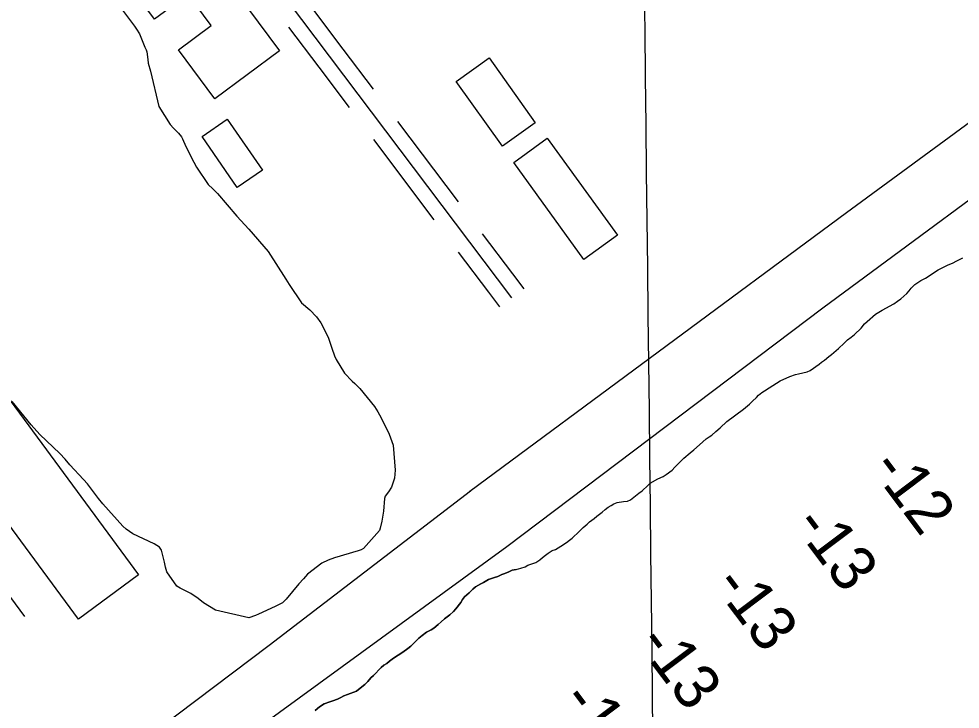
# Model space of a CAD drawing. Extents: x 3683613 to 3738215, y 469626 to 495384.
# Drawn here: x 3692332 to 3693268, y 490854 to 491540 of the extents above; entities that cross this region are included whole.
import ezdxf

# ---------------------------------------------------------------- set-up
doc = ezdxf.new("R2010")
doc.units = 0
for name, color, linetype in [('V-BLDG-OTLN', 7, 'Continuous'), ('V-GRID-MAJR', 7, 'Continuous'), ('V-LEVE-TOET', 7, 'Continuous'), ('V-ROAD-CNTR', 7, 'Continuous'), ('V-SITE-VEGE', 7, 'Continuous'), ('V-TOPO-SHOR', 7, 'Continuous'), ('V-TOPO-SPOT', 7, 'Continuous')]:
    doc.layers.add(name, color=color, linetype=linetype)

msp = doc.modelspace()

# ---------------------------------------------------------------- linework, layer by layer
at = {"layer": 'V-BLDG-OTLN'}
for points in [[(3692442.64, 491572.97000000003), (3692507.651, 491621.139), (3692591.333, 491508.2), (3692527.1890000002, 491460.677), (3692491.073, 491509.42100000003), (3692523.6180000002, 491533.534), (3692500.731, 491564.422), (3692467.318, 491539.664)], [(3692767.139, 491477.896), (3692799.823, 491501.163), (3692845.66, 491436.776), (3692812.9760000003, 491413.509)], [(3692539.414, 491440.41000000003), (3692574.386, 491389.74), (3692549.488, 491372.555), (3692514.52, 491423.227)], [(3692927.481, 491325.169), (3692894.085, 491300.976), (3692824.285, 491397.33400000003), (3692857.681, 491421.527)], [(3692184.004, 491350.224), (3692451.291, 490987.378), (3692391.522, 490943.35000000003), (3692124.237, 491306.196)]]:
    msp.add_lwpolyline(points, close=True, dxfattribs=at)
at = {"layer": 'V-GRID-MAJR'}
msp.add_spline([(3693141.066, 475101.816), (3693072.329, 481160.385), (3693003.5700000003, 487220.886), (3692934.811, 493281.396), (3692934.789, 493283.31700000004)], degree=3, dxfattribs=at)
at = {"layer": 'V-LEVE-TOET'}
for points in [[(3692780.816, 491070.70900000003), (3693154.944, 491347.748), (3693544.7460000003, 491633.896)], [(3693375.608, 491432.818), (3693131.521, 491252.477), (3692817.579, 491015.343)], [(3692069.132, 490545.9), (3692088.7970000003, 490552.982), (3692103.804, 490559.405), (3692117.5300000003, 490568.152), (3692133.363, 490579.45300000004), (3692229.812, 490654.031), (3692399.091, 490780.204), (3692581.236, 490917.664), (3692781.313, 491071.09)], [(3692817.579, 491015.343), (3692548.863, 490819.44800000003), (3692265.576, 490615.014), (3692133.869, 490516.549), (3692113.3910000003, 490501.84), (3692102.18, 490498.61), (3692097.312, 490497.95300000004), (3692084.799, 490501.707), (3692080.949, 490509.95), (3692077.098, 490517.767), (3692073.68, 490524.319), (3692071.3310000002, 490528.544), (3692067.055, 490536.78500000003), (3692066.187, 490541.864), (3692069.132, 490545.9)]]:
    msp.add_lwpolyline(points, dxfattribs=at)
at = {"layer": 'V-ROAD-CNTR'}
for points in [[(3692473.910013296, 491724.4935249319), (3692822.2133166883, 491262.82544826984)], [(3692624.404712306, 491549.9208740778), (3692654.518652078, 491510.0069539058)], [(3692600.4567602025, 491531.85291021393), (3692630.570699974, 491491.93899004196)], [(3692654.51765208, 491510.0069539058), (3692684.630591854, 491470.09303373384)], [(3692630.569699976, 491491.93899004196), (3692660.68263975, 491452.02506987)], [(3692708.721543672, 491438.16109759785), (3692768.948423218, 491358.3322572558)], [(3692684.773591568, 491420.093133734), (3692745.000471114, 491340.26429339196)], [(3692012.437936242, 491387.1261996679), (3692338.014285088, 490946.16108159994)], [(3692793.0403750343, 491326.40032112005), (3692823.153314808, 491286.48540094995)], [(3692769.090422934, 491308.332357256), (3692799.203362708, 491268.4174370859)], [(3692823.153314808, 491286.48640094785), (3692834.188292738, 491271.859430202)], [(3692799.203362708, 491268.41843708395), (3692810.238340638, 491253.7914663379)]]:
    msp.add_lwpolyline(points, dxfattribs=at)
at = {"layer": 'V-SITE-VEGE'}
for points in [[(3692425.293, 491562.24100000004), (3692447.457, 491532.903)], [(3692447.457, 491532.903), (3692449.378, 491529.735), (3692452.364, 491525.30100000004), (3692457.721, 491511.77), (3692458.792, 491509.233), (3692459.437, 491507.33), (3692460.531, 491499.498), (3692460.971, 491495.9), (3692463.128, 491488.07300000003), (3692471.549, 491452.954), (3692482.645, 491435.21400000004), (3692486.0530000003, 491431.417), (3692490.948, 491426.56700000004), (3692493.93, 491422.77), (3692494.997, 491420.868), (3692498.21, 491413.04600000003), (3692506.3310000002, 491397.623), (3692508.897, 491392.552), (3692520.626, 491375.449), (3692525.092, 491371.023), (3692529.774, 491366.598), (3692549.1520000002, 491344.025), (3692560.863, 491330.946), (3692580.028, 491308.797), (3692597.735, 491281.343), (3692600.936, 491276.064), (3692613.306, 491257.695), (3692621.598, 491250.744), (3692628.197, 491243.78500000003), (3692632.6720000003, 491237.875), (3692639.727, 491223.717), (3692643.379, 491212.721), (3692646.168, 491205.32), (3692647.878, 491201.514), (3692655.99, 491187.787), (3692663.65, 491179.984), (3692666.417, 491177.668), (3692671.311, 491172.609), (3692686.008, 491154.886), (3692689.2090000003, 491149.606), (3692692.627, 491143.689), (3692700.325, 491127.418), (3692704.403, 491116.422), (3692706.424, 491091.439), (3692705.613, 491083.599), (3692702.6890000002, 491074.69), (3692699.9590000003, 491070.016), (3692696.588, 491065.765), (3692695.752, 491063.219), (3692694.751, 491050.929), (3692693.315, 491040.757), (3692691.654, 491033.972), (3692690.816, 491031.639), (3692675.014, 491013.772), (3692672.477, 491012.49), (3692669.73, 491011.419), (3692646.254, 491004.321), (3692639.698, 491001.95900000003), (3692633.569, 490999.178), (3692619.429, 490988.099), (3692615.214, 490983.632), (3692610.578, 490978.526), (3692597.94, 490963.43), (3692594.358, 490959.814), (3692587.173, 490955.967), (3692570.6890000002, 490948.265), (3692567.517, 490946.981), (3692560.961, 490944.83), (3692527.886, 490952.512), (3692515.991, 490959.66000000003), (3692510.461, 490964.086), (3692503.238, 490968.92100000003), (3692492.625, 490974.166), (3692489.2260000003, 490976.267), (3692479.418, 490990.41500000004), (3692478.123, 490995.27900000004), (3692477.042, 491000.147)], [(3692477.042, 491000.147), (3692474.023, 491011.993), (3692472.102, 491014.95), (3692467.003, 491018.315), (3692445.775, 491028.38300000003), (3692438.978, 491033.009), (3692435.576, 491035.74700000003), (3692415.774, 491058.107), (3692411.514, 491063.38300000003), (3692409.595, 491066.125), (3692400.433, 491077.944), (3692396.599, 491082.374), (3692383.19, 491096.927), (3692378.503, 491102.412), (3692372.971, 491108.105), (3692353.185, 491126.863), (3692344.457, 491136.568), (3692325.7090000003, 491159.776)]]:
    msp.add_lwpolyline(points, dxfattribs=at)
at = {"layer": 'V-TOPO-SHOR'}
for points in [[(3692826.7630000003, 490992.663), (3692831.387, 490994.191), (3692835.798, 490995.518), (3692838.342, 490997.11), (3692846.1240000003, 490999.793), (3692850.364, 491002.373), (3692852.932, 491004.79600000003), (3692855.705, 491007.004), (3692858.679, 491008.996), (3692862.5, 491011.58900000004), (3692865.865, 491012.74), (3692870.954, 491015.92100000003), (3692876.681, 491019.498), (3692879.875, 491021.901), (3692882.225, 491023.914), (3692889.497, 491030.568), (3692893.151, 491034.414), (3692897.208, 491037.83400000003), (3692899.77, 491040.048), (3692904.2430000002, 491043.454), (3692907.02, 491045.871), (3692912.127, 491049.674), (3692915.333, 491052.494), (3692918.312, 491054.695), (3692921.2800000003, 491056.481), (3692923.824, 491058.07300000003), (3692927.1950000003, 491059.428), (3692933.466, 491060.284), (3692937.4280000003, 491060.583), (3692940.384, 491061.95300000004), (3692943.583, 491064.565), (3692948.4960000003, 491068.792), (3692951.8910000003, 491070.981), (3692957.673, 491076.431), (3692960.028, 491078.651), (3692967.645, 491082.798), (3692972.7090000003, 491085.145), (3692975.683, 491087.14), (3692981.85, 491091.537), (3692984.43, 491094.373), (3692993.441, 491103.47500000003), (3692999.6380000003, 491108.912), (3693003.261, 491111.72000000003), (3693008.822, 491116.76), (3693012.242, 491119.781), (3693015.449, 491122.601), (3693018.427, 491124.803), (3693021.179, 491126.386), (3693025.236, 491129.804), (3693029.5130000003, 491133.63300000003), (3693036.15, 491139.89), (3693052.544, 491152.311), (3693058.723, 491157.124), (3693061.722, 491159.95), (3693065.582, 491163.79000000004), (3693067.736, 491166.22500000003), (3693070.929, 491168.63), (3693073.682, 491170.213), (3693078.355, 491173.406), (3693085.568, 491177.981), (3693089.173, 491180.162), (3693098.8740000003, 491184.457), (3693104.349, 491186.585), (3693107.492, 491187.324), (3693116.082, 491189.153), (3693119.037, 491190.523), (3693127.753, 491196.718), (3693130.102, 491198.729), (3693133.082, 491200.931), (3693137.561, 491204.545), (3693140.326, 491206.544), (3693144.811, 491210.368), (3693147.16, 491212.379), (3693152.733, 491217.837), (3693156.159, 491221.065), (3693159.7800000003, 491223.87200000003), (3693162.973, 491226.277), (3693169.61, 491232.533), (3693173.0670000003, 491236.80100000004), (3693175.644, 491239.431), (3693183.762, 491246.478), (3693187.151, 491248.45900000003), (3693190.541, 491250.439), (3693202.182, 491256.966), (3693205.79, 491259.356), (3693208.985, 491261.76), (3693215.182, 491267.19800000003), (3693217.341, 491269.84), (3693219.495, 491272.275), (3693223.147, 491276.121), (3693228.8850000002, 491280.115), (3693233.534, 491282.476), (3693236.289, 491284.059), (3693242.453, 491288.456), (3693246.265, 491290.63300000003), (3693251.544, 491293.185), (3693255.559, 491295.147), (3693261.252, 491297.684), (3693264.213, 491299.26300000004), (3693270.767, 491302.608)], [(3693127.753, 491196.718), (3693130.102, 491198.729), (3693133.082, 491200.931), (3693137.561, 491204.545), (3693140.326, 491206.544), (3693144.811, 491210.368), (3693147.16, 491212.379), (3693152.733, 491217.837), (3693156.159, 491221.065), (3693159.7800000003, 491223.87200000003), (3693162.973, 491226.277), (3693169.61, 491232.533), (3693173.0670000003, 491236.80100000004), (3693175.644, 491239.431), (3693183.762, 491246.478), (3693187.151, 491248.45900000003), (3693190.541, 491250.439), (3693202.182, 491256.966), (3693205.79, 491259.356), (3693208.985, 491261.76), (3693215.182, 491267.19800000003), (3693217.341, 491269.84), (3693219.495, 491272.275), (3693223.147, 491276.121), (3693228.8850000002, 491280.115), (3693233.534, 491282.476), (3693236.289, 491284.059), (3693242.453, 491288.456), (3693246.265, 491290.63300000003), (3693251.544, 491293.185), (3693255.559, 491295.147), (3693261.252, 491297.684), (3693264.213, 491299.26300000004), (3693270.767, 491302.608)], [(3692697.997, 490899.506), (3692700.952, 490901.849), (3692704.751, 490904.62200000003), (3692714.041, 490910.80700000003), (3692719.1070000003, 490914.43200000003), (3692722.063, 490916.564), (3692724.381, 490918.903), (3692727.754, 490922.096), (3692730.075, 490924.436), (3692733.239, 490927.205), (3692737.46, 490930.613), (3692742.3200000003, 490932.753), (3692744.853, 490934.672), (3692749.072, 490938.291), (3692752.238, 490940.849), (3692755.611, 490943.829), (3692760.6780000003, 490947.66500000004), (3692764.475, 490951.07300000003), (3692766.791, 490953.625), (3692771.6350000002, 490960.00200000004), (3692773.5270000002, 490962.976), (3692775.421, 490965.525), (3692780.062, 490969.57), (3692783.644, 490973.4), (3692786.3880000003, 490975.532), (3692791.457, 490978.52), (3692794.204, 490980.015), (3692799.063, 490982.79000000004), (3692805.1950000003, 490984.938), (3692808.578, 490986.012), (3692812.384, 490987.724), (3692815.343, 490988.797), (3692819.359, 490990.509), (3692822.74, 490992.219), (3692826.7630000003, 490992.663), (3692831.387, 490994.191), (3692835.798, 490995.518), (3692838.342, 490997.11), (3692846.1240000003, 490999.793), (3692850.364, 491002.373), (3692852.932, 491004.79600000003), (3692855.705, 491007.004), (3692858.679, 491008.996), (3692862.5, 491011.58900000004), (3692865.865, 491012.74), (3692870.954, 491015.92100000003), (3692876.681, 491019.498), (3692879.875, 491021.901), (3692882.225, 491023.914), (3692889.497, 491030.568), (3692893.151, 491034.414), (3692897.208, 491037.83400000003), (3692899.77, 491040.048), (3692904.2430000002, 491043.454), (3692907.02, 491045.871), (3692912.127, 491049.674), (3692915.333, 491052.494), (3692918.312, 491054.695), (3692921.2800000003, 491056.481), (3692923.824, 491058.07300000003), (3692927.1950000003, 491059.428), (3692933.466, 491060.284), (3692937.4280000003, 491060.583), (3692940.384, 491061.95300000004), (3692943.583, 491064.565), (3692948.4960000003, 491068.792), (3692951.8910000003, 491070.981), (3692957.673, 491076.431), (3692960.028, 491078.651), (3692967.645, 491082.798), (3692972.7090000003, 491085.145), (3692975.683, 491087.14), (3692981.85, 491091.537), (3692984.43, 491094.373), (3692993.441, 491103.47500000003), (3692999.6380000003, 491108.912), (3693003.261, 491111.72000000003), (3693008.822, 491116.76), (3693012.242, 491119.781), (3693015.449, 491122.601), (3693018.427, 491124.803), (3693021.179, 491126.386), (3693025.236, 491129.804), (3693029.5130000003, 491133.63300000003), (3693036.15, 491139.89), (3693052.544, 491152.311), (3693058.723, 491157.124), (3693061.722, 491159.95), (3693065.582, 491163.79000000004), (3693067.736, 491166.22500000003), (3693070.929, 491168.63), (3693073.682, 491170.213), (3693078.355, 491173.406), (3693085.568, 491177.981), (3693089.173, 491180.162), (3693098.8740000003, 491184.457), (3693104.349, 491186.585), (3693107.492, 491187.324), (3693116.082, 491189.153), (3693119.037, 491190.523), (3693127.753, 491196.718)], [(3692826.7630000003, 490992.663), (3692822.74, 490992.219), (3692819.359, 490990.509), (3692815.343, 490988.797), (3692812.384, 490987.724), (3692808.578, 490986.012), (3692805.1950000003, 490984.938), (3692799.063, 490982.79000000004), (3692794.204, 490980.015), (3692791.457, 490978.52), (3692786.3880000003, 490975.532), (3692783.644, 490973.4), (3692780.062, 490969.57), (3692775.421, 490965.525), (3692773.5270000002, 490962.976), (3692771.6350000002, 490960.00200000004), (3692766.791, 490953.625), (3692764.475, 490951.07300000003), (3692760.6780000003, 490947.66500000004), (3692755.611, 490943.829), (3692752.238, 490940.849), (3692749.072, 490938.291), (3692744.853, 490934.672), (3692742.3200000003, 490932.753), (3692737.46, 490930.613), (3692733.239, 490927.205), (3692730.075, 490924.436), (3692727.754, 490922.096), (3692724.381, 490918.903), (3692722.063, 490916.564), (3692719.1070000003, 490914.43200000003), (3692714.041, 490910.80700000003), (3692704.751, 490904.62200000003), (3692700.952, 490901.849), (3692697.997, 490899.506), (3692695.252, 490897.587), (3692692.508, 490895.457), (3692684.92, 490887.585), (3692682.3910000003, 490885.033), (3692679.2290000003, 490881.62700000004), (3692676.278, 490878.64900000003), (3692671.637, 490874.815), (3692668.049, 490871.83400000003), (3692658.9560000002, 490868.614), (3692655.363, 490867.115), (3692652.404, 490865.62), (3692649.023, 490863.908), (3692644.585, 490862.194), (3692641.41, 490861.331), (3692635.914, 490859.4), (3692631.056, 490856.199), (3692627.048, 490852.793)], [(3692627.048, 490852.793), (3692631.056, 490856.199), (3692635.914, 490859.4), (3692641.41, 490861.331), (3692644.585, 490862.194), (3692649.023, 490863.908), (3692652.404, 490865.62), (3692655.363, 490867.115), (3692658.9560000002, 490868.614), (3692668.049, 490871.83400000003), (3692671.637, 490874.815), (3692676.278, 490878.64900000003), (3692679.2290000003, 490881.62700000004), (3692682.3910000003, 490885.033), (3692684.92, 490887.585), (3692692.508, 490895.457), (3692695.252, 490897.587), (3692697.997, 490899.506)]]:
    msp.add_lwpolyline(points, dxfattribs=at)

# ---------------------------------------------------------------- texts
at = {"layer": 'V-TOPO-SPOT'}
for s, p in [('-12', (3693177.8770559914, 491093.6784112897)), ('-13', (3693101.2893535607, 491037.02035171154)), ('-13', (3693021.6593535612, 490977.4703517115)), ('-13', (3692945.7793535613, 490919.27035171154)), ('-13', (3692869.819353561, 490862.65035171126))]:
    msp.add_text(s, height=45, rotation=306.93472757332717, dxfattribs=at).set_placement(p)

doc.saveas('drawing.dxf')
